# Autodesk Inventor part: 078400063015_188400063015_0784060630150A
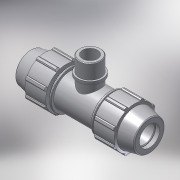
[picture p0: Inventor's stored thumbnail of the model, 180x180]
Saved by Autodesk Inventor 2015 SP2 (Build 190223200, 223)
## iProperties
Created: 2017-02
Part Number: 078400063015_188400063015_0784060630150A
Material: PVC-Piping
Description: PLASSON TEE WITH THREADED MALE OFFTAKE 63-1.1/2"-63
Document SubType Name: Modeling
Designer: KIM
Mass: 92.6774 g
Surface Area: 199.44 cm^2
Volume: 66.1981 cm^3
Density: 1.4 g/cm^3
Appearance: Smooth - White
Author: Кирилл
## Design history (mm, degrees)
derived "07840.ipt"
feature "Solid1::07840.ipt"
feature "Solid2::07840.ipt"
tag "TaggingFeature1"
body "Solid1"
body "Solid2"
other parameters: "d2" = 63, "d4" = 11.16667, "d5" = 32.16, "d7" = 113, "d11" = 4.46667, "d13" = 120 deg, "d14" = 94.5, "d15" = 12 deg, "d16" = 98.31, "d18" = 3.15, "d19" = 35 deg, "d20" = 17.5 deg, "d21" = 105.09, "d23" = 0, "d25" = 360 deg, "d27" = 2.26, "d33" = 1.26, "d42" = 48.24, "d43" = 3.39, "d46" = 1.89, "d68" = 4.46667, "d72" = 83, "d73" = 47.803, "d74" = 22, "d75" = 54.97345, "d76" = 33.4621, "d77" = 26.4, "d80" = 1.43409, "d91" = 84.75, "d93" = 113, "d95" = 56.7, "d99" = 268, "d101" = 0, "d103" = 0, "d105" = 0, "d_" = 63, "E_" = 113, "A_" = 83, "l_" = 113, "l_2" = 22, "H_" = 268, "R_" = 47.803
